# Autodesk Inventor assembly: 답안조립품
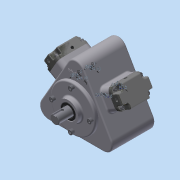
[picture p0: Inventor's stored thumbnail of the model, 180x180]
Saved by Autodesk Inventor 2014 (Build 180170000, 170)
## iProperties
Created: 2015-06
Part Number: 답안조립품
Document SubType Name: Assembly
Designer: Administrator
Mass: 5318.58 g
Surface Area: 2414.93 cm^2
Volume: 1564.62 cm^3
Density: 3.39928 g/cm^3
Author: Administrator
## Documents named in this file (20)
- C:\Users\Administrator\Desktop\350605V1040\답안조립품.iam
- C:\Users\Administrator\Desktop\350605V1040\본체.ipt
- C:\Users\Administrator\Desktop\350605V1040\베어링 NA 4904.ipt
- 베어링 NA 4904.ipt
- C:\Users\Administrator\Desktop\350605V1040\앞커버.ipt
- C:\Users\Administrator\Desktop\350605V1040\오일실.ipt
- 오일실.ipt
- C:\Users\Administrator\Desktop\350605V1040\편심축.ipt
- C:\Users\Administrator\Desktop\350605V1040\부시.ipt
- C:\Users\Administrator\Desktop\350605V1040\M6x0.7x20.ipt
- M6x0.7x20.ipt
- C:\Users\Administrator\Desktop\350605V1040\슬라이드.ipt
- C:\Users\Administrator\Desktop\350605V1040\M4x0.5x16.ipt
- M4x0.5x16.ipt
- C:\Users\Administrator\Desktop\350605V1040\헤더커버.ipt
- 헤더커버.ipt
- C:\Users\Administrator\Desktop\350605V1040\8-스프링.ipt
- C:\Users\Administrator\Desktop\350605V1040\9-스프링.ipt
- C:\Users\Administrator\Desktop\350605V1040\10-스프링.ipt
- C:\Users\Administrator\Desktop\350605V1040\11-스프링.ipt
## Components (18 placed, 7 different names)
1. M4x0.5x16:1
2. 헤더커버:1
3. M4x0.5x16:2
4. 헤더커버:2
5. M4x0.5x16:3
6. M4x0.5x16:4
7. M4x0.5x16:5
8. M4x0.5x16:6
9. M4x0.5x16:7
10. M4x0.5x16:8
11. 8-스프링:1
12. 9-스프링:1
13. 10-스프링:1
14. 11-스프링:1
15. M6x0.7x20:1
16. M6x0.7x20:2
17. M6x0.7x20:3
18. M6x0.7x20:4
